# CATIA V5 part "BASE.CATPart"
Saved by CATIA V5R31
Part number: BASE
Revision: 01
Nomenclature: BASE
Source: Unknown
Property "部品番号(B社)": "MOLD333333"
Property "部品名称(B社)": "BASE"
Property "Version(B社)": "01"
Property "材質(B社)": "PBT"
Bounding box of the stored display mesh (mm): x -10 to 11.5, y -14.75 to 14.75, z -47 to 7.95
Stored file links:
  \\solize.local\damia\dept\DDE_Design\10_order\2305701_JAMA_変換検証STEP3_お手本モデル作成\work\03_東洋電装_スイッチ\10_CATIA_V5\BASE.CATPart
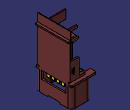
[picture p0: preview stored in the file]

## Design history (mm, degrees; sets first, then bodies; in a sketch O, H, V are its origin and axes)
WSupportSet1: ActiveGrid {3dwsupport RefPoint {point stored without definition}, 3DWOS ({wsupport Support xy-plane, RefPoint {3dwsupport}, GridIn {cartgrid Value 100, Stepbid1 0, Value 100, Stepbid2 0, Direction (1, 0, 0)}, GeometricData ({line type PtDir, Direction (1, 0, 0), Support xy-plane}; {line type PtDir, Direction (0, 1, 0), Support xy-plane})}; {wsupport Support yz-plane, RefPoint {3dwsupport}, GridIn {cartgrid Value 100, Stepbid1 0, Value 100, Stepbid2 0, Direction (0, 1, 0)}, GeometricData ({line type PtDir, Direction (0, 1, 0), Support yz-plane}; {line type PtDir, Direction (0, 0, 1), Support yz-plane})}; {wsupport Support zx-plane, RefPoint {3dwsupport}, GridIn {cartgrid Value 100, Stepbid1 0, Value 100, Stepbid2 0, Direction (0, 0, 1)}, GeometricData ({line type PtDir, Direction (0, 0, 1), Support zx-plane}; {line type PtDir, Direction (1, 0, 0), Support zx-plane})}), GeometricData ({line type PtDir, RefPoint {point stored without definition}, Direction (1, 0, 0), Support xy-plane}; {line type PtDir, RefPoint {point stored without definition}, Direction (0, 1, 0), Support xy-plane}; {line type PtDir, RefPoint {point stored without definition}, Direction (0, 1, 0), Support yz-plane}; {line type PtDir, RefPoint {point stored without definition}, Direction (0, 0, 1), Support yz-plane}; {line type PtDir, RefPoint {point stored without definition}, Direction (0, 0, 1), Support zx-plane}; {line type PtDir, RefPoint {point stored without definition}, Direction (1, 0, 0), Support zx-plane})}
Body1 (main body)
  Solid1 "PartBody": solid without history
Body2 "TERMINAL"
  Solid2: solid without history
